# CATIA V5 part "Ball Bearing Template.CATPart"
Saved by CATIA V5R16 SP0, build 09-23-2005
Part number: Ball Bering Template
Bounding box of the stored display mesh (mm): x -4.499 to 4.499, y -2 to 2, z -4.499 to 4.499
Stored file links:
  E:\#01 CATIA Lecture Materials\#06 DMU\#16 DMU Page01 KIN EX16\Ball Bearing Template.CATPart
  C:\Program Files\Dassault Systemes\B20\win_b64\startup\materials\Catalog.CATMaterial
  E:\#01 CATIA Lecture Materials\#05 KWA\#04 KWA10(Bearing)\#02 Document\Ball Bearing DesignTable.xls
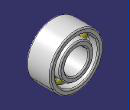
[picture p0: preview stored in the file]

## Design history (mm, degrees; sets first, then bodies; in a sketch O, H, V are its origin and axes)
External parameters (linked from other documents)
  External.D = 9 mm
  External.d = 4 mm
  External.B = 4 mm
  External.r = 0.2 mm
  External.s = 0.65 mm {= (External.D -External.d )*0.13}
  External.Z = 11 {= int((External.D + External.d ) / (External.s * 2) ) +1}
  `External.Bearing Number` = "6200"
Set1 "Reference Data"
  Point1 "Center Point": (0, 0, 0)
  Point2: (0, 0, 3.25 {= (External.D+External.d)/4}), relative to Point1
  Sphere1 "Ball": Center Point2, Radius 0.65 {= External.s}, Angle1 -45, Angle3 0, Angle4 180
Body1 "PartBody" (main body)
  Body2 "Body.1"
    Sketch1 on xy-plane, origin (0, 0, 0), H (1, 0, 0), V (0, 1, 0)
      axis line L1 (0, 0) -> (0, 87.7764)
      construction line L2 (3.25, 0) -> (3.25, 15.0879)
      point P2 (3.25, 0)
      line L3 (2, 2) -> (4.5, 2)
      line L4 (4.5, 2) -> (4.5, -2)
      line L5 (4.5, -2) -> (2, -2)
      line L6 (2, -2) -> (2, 2)
      distance L3 L5 = 4 {= External.B}
      distance L1 L6 = 2 {= External.d /2}
      distance L1 L4 = 4.5 {= External.D /2}
      vertical: L1 V, L2 V, L4 V, L6 V
      coincidence: P2 H
      horizontal: L3 H, L5 H
      symmetry: L6 L4 L2, L3 L5 H
    Shaft1: profile Sketch1, axis Sketch1.L1, angle 360
    Sketch2 on xy-plane, origin (0, 0, 0), H (1, 0, 0), V (0, 1, 0)
      axis line L1 (0, 0) -> (0, 17.8821)
      line L2 (2.875, 2) -> (3.625, 2)
      line L3 (3.625, 2) -> (3.625, 0.5309)
      line L4 (3.625, -2) -> (2.875, -2)
      line L5 (2.875, -2) -> (2.875, -0.5309)
      arc A1 centre (3.25, 0) radius 0.65 from (2.875, 0.5309) to (2.875, -0.5309) ccw
      point P6 (3.25, 0)
      construction line L6 (3.25, 0) -> (3.25, 2)
      point P7 (3.25, 2)
      point P8 (3.625, -0.5309)
      line L7 (3.625, -0.5309) -> (3.625, -2)
      point P10 (2.875, 0.5309)
      line L8 (2.875, 0.5309) -> (2.875, 2)
      arc A2 centre (3.25, 0) radius 0.65 from (3.625, -0.5309) to (3.625, 0.5309) ccw
      distance L5 L3 = 0.75 {= (External.D - External.d) * 0.15}
      radius A1 = 0.65 {= External.s}
      distance L2 L4 = 4 {= External.B}
      distance L6 L1 = 3.25 {= Point2.Z}
      vertical: L1 V, L3 V, L5 V, L6 V, L7 V, L8 V
      horizontal: L2 H, L4 H
      coincidence: P6 H, A1 P8, L3 L7, L5 P10, L5 L8, A1 A2
      midpoint: P7 L2
      symmetry: L5 L3 L6, L2 L4 H
    Groove1: profile Sketch2, axis Sketch2.L1, angle 360
    Fillet1: radius 0.2 {= External.r}, on face of Shaft1 from Sketch1.L4; edge [face of Shaft1 from Sketch1.L6 | face of Shaft1 from Sketch1.L5]; edge [face of Shaft1 from Sketch1.L3 | face of Shaft1 from Sketch1.L6]; edge [face of Groove1 from Sketch2.L7 | face of Shaft1 from Sketch1.L5]; edge [face of Shaft1 from Sketch1.L5 | face of Groove1 from Sketch2.L5]; edge [face of Shaft1 from Sketch1.L3 | face of Groove1 from Sketch2.L3]; edge [face of Groove1 from Sketch2.L8 | face of Shaft1 from Sketch1.L3]
  Assemble1: tool Body2
  Body3
    CloseSurface1: CloseElement Sphere1
    CircPattern1: of the body so far, instances 11 {= External.Z}, angular step 32.7273 {= 360.0*1 deg/CircPattern1.AngularNumber}, axis from zx-plane
  Assemble2: tool Body3
Relations
  rule (deactivated):
    if `External.Bearing Number` =="6200"
    	{
    		External.D = 30mm
    		External.d = 10mm
    		External.B = 9mm
    		External.r = 0.61mm
    	}
    else if `External.Bearing Number` =="6201"
    	{
    		External.D = 32mm
    		External.d = 12mm
    		External.B = 10mm
    		External.r = 0.61mm
    	}
    else if `External.Bearing Number` =="6202"
    	{
    		External.D = 35mm
    		External.d = 15mm
    		External.B = 11mm
    		External.r = 0.61mm
    	}
    else if `External.Bearing Number` =="6203"
    	{
    		External.D = 40mm
    		External.d = 17mm
    		External.B = 12mm
    		External.r = 0.61mm
    	}
    else if `External.Bearing Number` =="6204"
    	{
    		External.D = 47mm
    		External.d = 20mm
    		External.B = 14mm
    		External.r = 0.975mm
    	}
    else if `External.Bearing Number` =="6205"
    	{
    		External.D = 52mm
    		External.d = 25mm
    		External.B = 15mm
    		External.r = 0.975mm
    	}
    else if `External.Bearing Number` =="6206"
    	{
    		External.D = 62mm
    		External.d = 30mm
    		External.B = 16mm
    		External.r = 0.975mm
    	}
    else if `External.Bearing Number` =="6207"
    	{
    		External.D = 72mm
    		External.d = 35mm
    		External.B = 17mm
    		External.r = 0.975mm
    	}
    else if `External.Bearing Number` =="6208"
    	{
    		External.D = 80mm
    		External.d = 40mm
    		External.B = 18mm
    		External.r = 0.975mm
    	}
    else if `External.Bearing Number` =="6209"
    	{
    		External.D = 85mm
    		External.d = 45mm
    		External.B = 19mm
    		External.r = 0.975mm
    	}
    else
    	{
    		External.D = 90mm
    		External.d = 50mm
    		External.B = 20mm
    		External.r = 0.975mm
    	}
  design table "Ball Bearing Design Table", configuration 1, drives `External.Bearing Number`, External.D, External.d, External.B, External.r (deactivated)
